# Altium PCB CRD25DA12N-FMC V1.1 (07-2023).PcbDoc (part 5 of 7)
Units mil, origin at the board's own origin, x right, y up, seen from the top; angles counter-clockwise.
Board outline 8000 x 8000 mil, 6 copper layers (Top Layer, Layer 2, Layer 3, Layer 4, Layer 5, Bottom Layer), stack 91 mil thick; 542 components, 315 nets, 1585 pads, 558 vias.
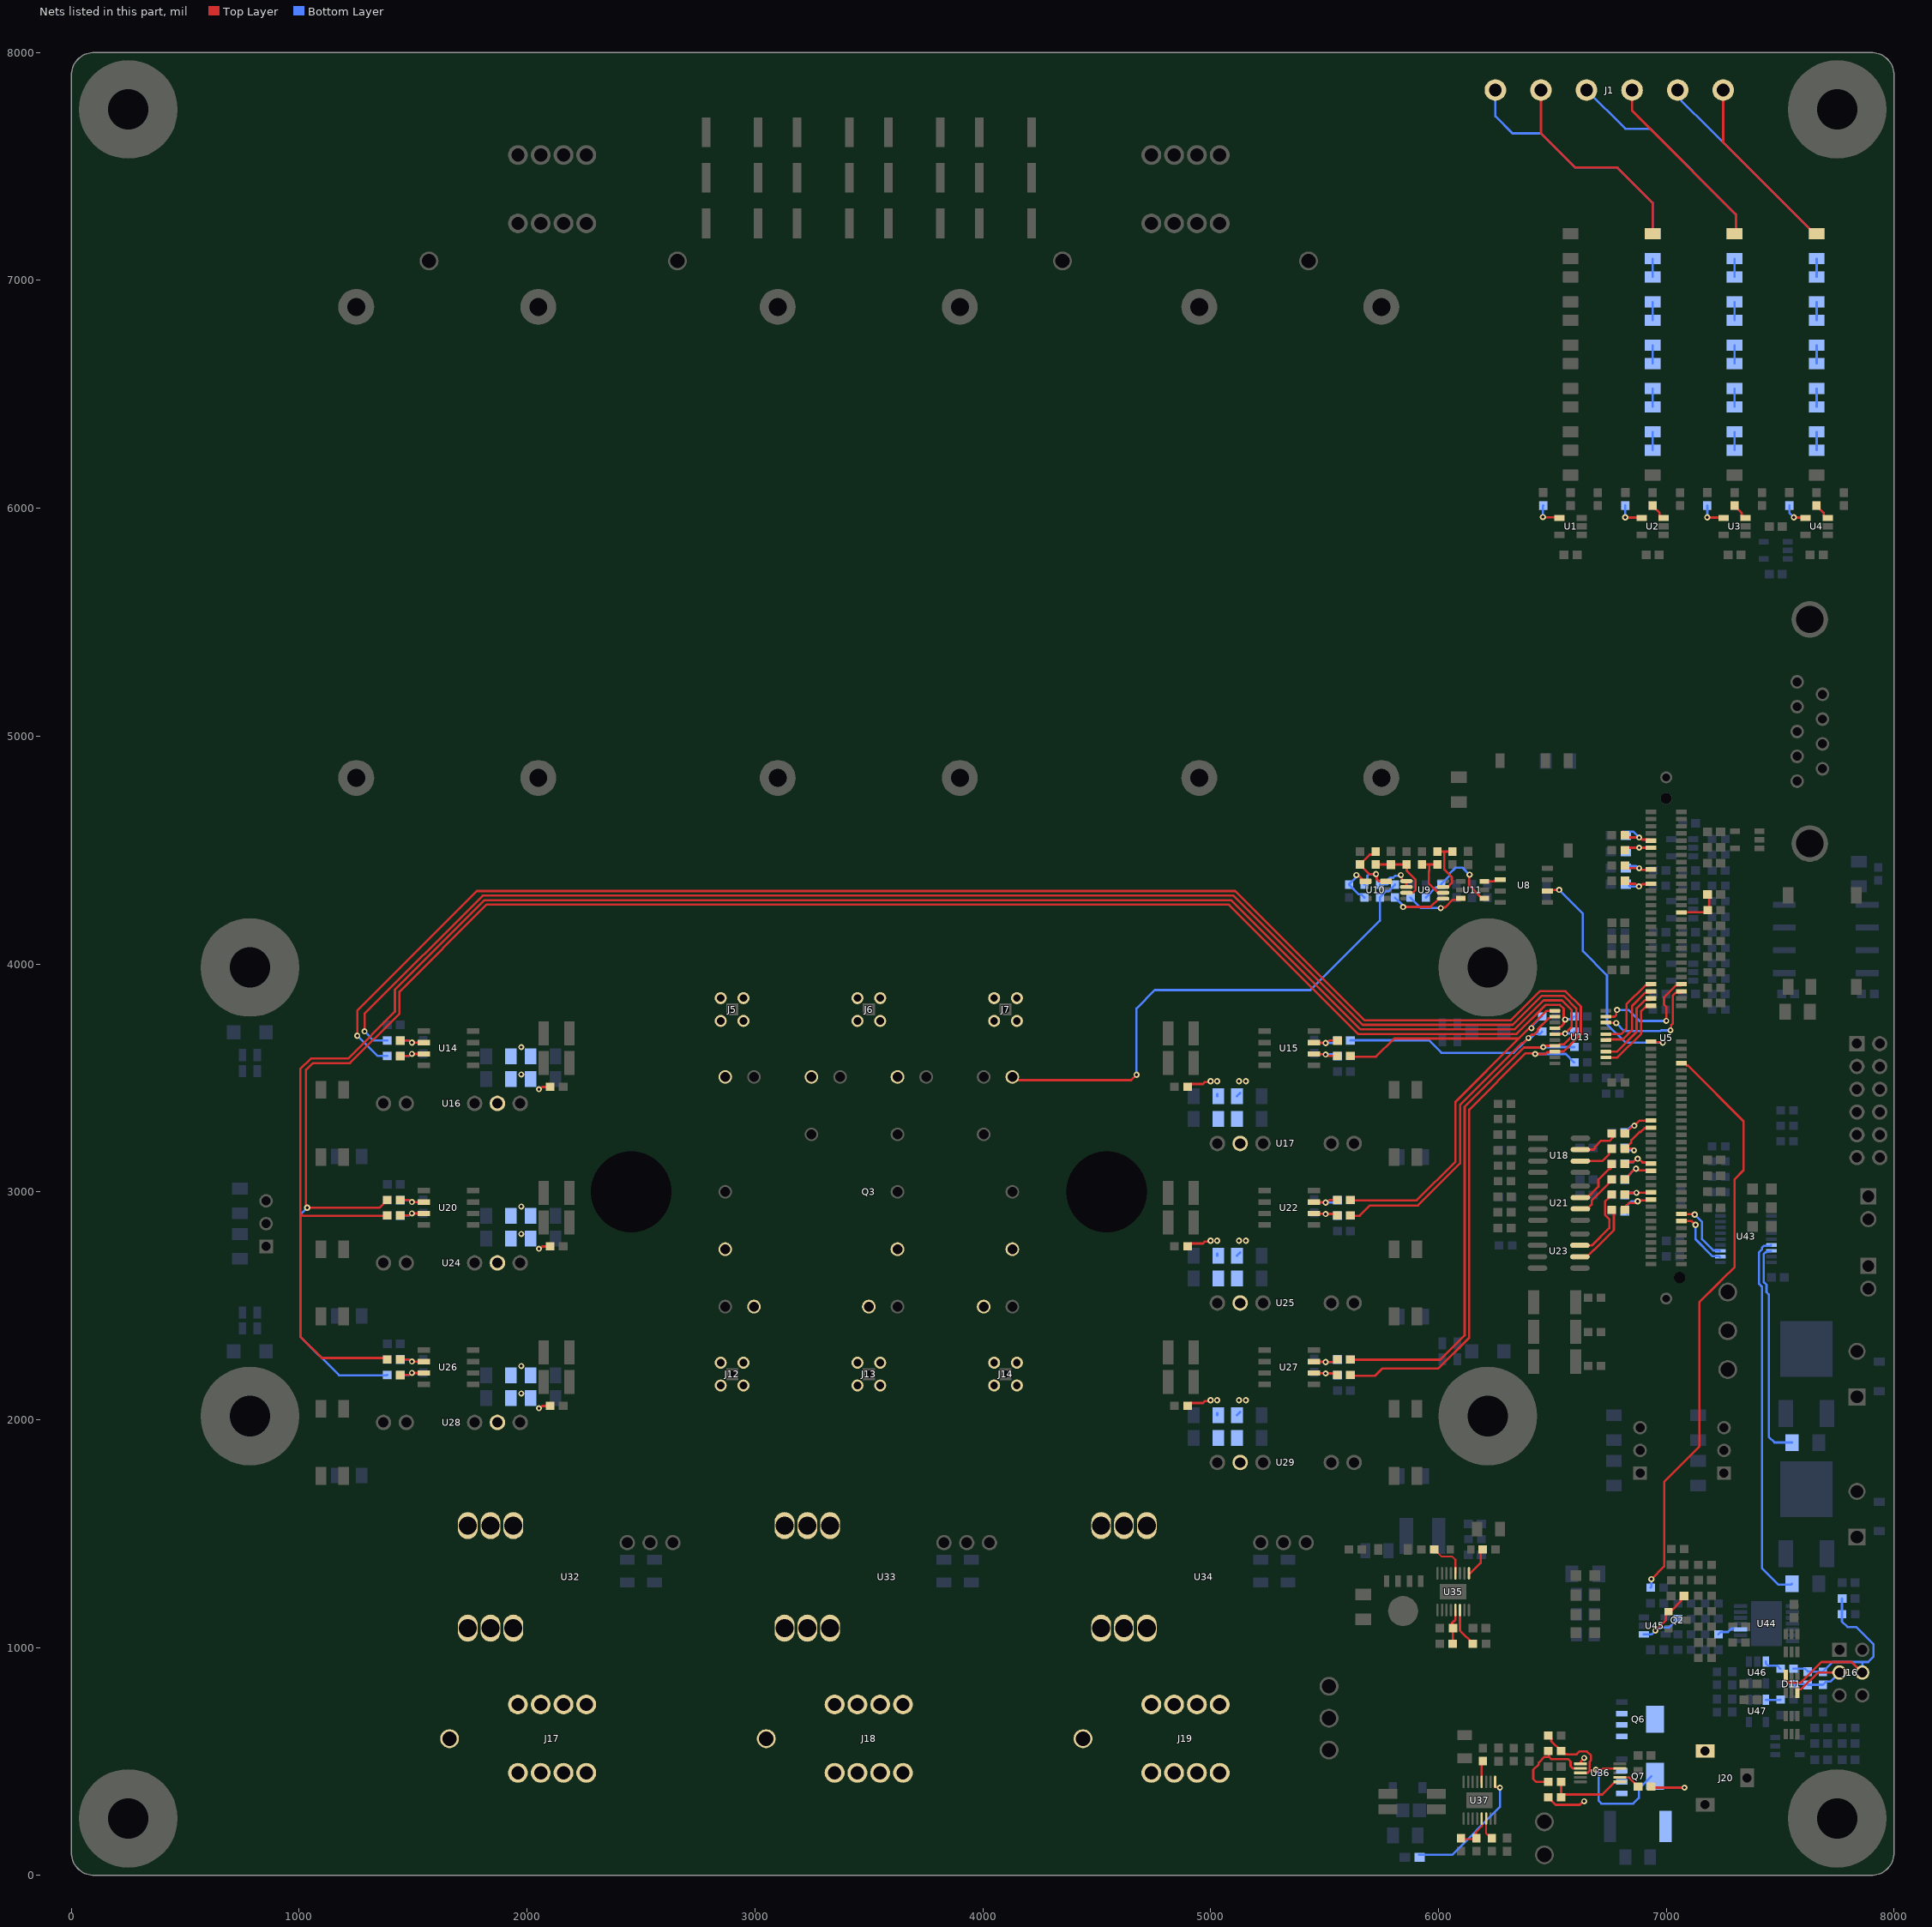
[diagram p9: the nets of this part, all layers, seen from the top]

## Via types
v1: diameter 27, hole 13, Top Layer to Bottom Layer, tented both sides, 455 vias
v2: diameter 50, hole 28, Top Layer to Bottom Layer, tented both sides, 76 vias
v3: diameter 19.68, hole 7.87, Top Layer to Bottom Layer, 27 vias

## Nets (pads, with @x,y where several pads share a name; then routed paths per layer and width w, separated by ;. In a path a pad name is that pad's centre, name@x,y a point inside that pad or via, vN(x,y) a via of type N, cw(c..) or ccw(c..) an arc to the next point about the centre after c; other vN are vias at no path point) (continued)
NetR39_2: R39.2 U2.3 | length 84.1
  Top Layer w10: R39.2@6940,6011.38 6940,6010.47 6970.59,5979.88 6970.59,5961.18 6979.37,5952.4 U2.3@6988.23,5952.4
NetR41_2: R41.2 U3.3 | length 79.1
  Top Layer w10: R41.2@7300,6011.38 7300,6010.47 7330.59,5979.88 7330.59,5966.18 7339.37,5957.4 U3.3@7348.23,5957.4
NetR43_2: R43.2 U4.3 | length 79.1
  Top Layer w10: R43.2@7660,6011.38 7660,6010.47 7690.59,5979.88 7690.59,5966.18 7699.37,5957.4 U4.3@7708.23,5957.4
NetR47_1: R47.1 R48.2 R162.2 U10.3 | length 341.8
  Top Layer w10: R47.1@5656,4436.38 5656,4435.47 5697.46,4394.02 v1(5726.14,4394.02) ; R47.1@5656,4437.28 5698.48,4479.76 5711.04,4479.76 5724,4492.72 R48.2@5724,4493.62 ; v1@5723.56,4391.44 5724.11,4391.44 5729.39,4386.16 5729.39,4372.11 5739.09,4362.4 U10.3@5780.08,4362.4
  Bottom Layer w10: R162.2@5675,4348.62 5687.96,4361.58 5687.96,4387.16 5694.81,4394.02 v1(5726.14,4394.02)
NetR50_2: R50.2 R51.1 U9.6 | length 227
  Top Layer w10: R50.2@5928,4436.38 5960,4436.38 ; R51.1@5991,4436.83 5990.54,4436.38 5960,4436.38 ; U9.6@6020.71,4312.2 5999.92,4312.2 5994.19,4317.94 5993.78,4317.94 5957.51,4354.21 5957.51,4406.31 5960,4408.8 5960,4436.38
NetR51_2: R51.2 R52.2 U9.7 | length 266.5
  Top Layer w10: R51.2@5991,4493.17 6026.27,4493.17 ; U9.7@6022.19,4339.27 6042.97,4339.27 6047.23,4343.53 6047.64,4343.53 6059.27,4355.16 6059.27,4368.13 6058.48,4368.91 6058.48,4381.68 6026.27,4413.89 6026.27,4493.17 ; R52.2@6062,4493.62 6061.54,4493.17 6026.27,4493.17
NetR68_1: R68.1 U18.7 | length 154.9
  Top Layer w10: U18.7@6638.06,3185 6680.64,3185 6686.5,3190.86 6686.5,3196.81 6714.03,3224.33 6752.28,3224.33 6765,3237.05 R68.1@6765,3240
NetR69_1: R69.1 U18.6 | length 152.8
  Top Layer w10: U18.6@6638.06,3135 6720,3135 6748.67,3163.67 6748.67,3176.04 6752.63,3180 R69.1@6765,3180
NetR70_1: R70.1 U21.7 | length 219.8
  Top Layer w10: U21.7@6623.06,2975 6654.3,2975 6702.21,3022.91 6702.21,3053.89 6747.65,3099.33 6752.28,3099.33 6765,3112.05 R70.1@6765,3115
NetR72_1: R72.1 U21.6 | length 206.2
  Top Layer w10: U21.6@6623.06,2925 6654.3,2925 6673,2943.7 6673,2961.94 6703.48,2992.42 6703.48,2992.62 6762.91,3052.05 R72.1@6762.91,3055
NetR76_1: R76.1 U23.7 | length 333.6
  Top Layer w10: U23.7@6621.11,2765 6675,2765 6750,2840 6750,2880 6731.22,2898.78 6731.22,2956.81 6747.52,2973.11 6747.52,2975.04 R76.1@6764.52,2992.05
NetR79_1: R79.1 U23.6 | length 290.1
  Top Layer w10: U23.6@6621.11,2715 6652.35,2715 6682.35,2745 6683.28,2745 6770,2831.72 6770,2912.38 R79.1@6761.38,2921
NetR99_1: R99.1 U35.4 | length 170.7
  Top Layer w8: R99.1@5983.15,1430 6013.15,1400 6060.21,1400 6074.84,1385.37 U35.4@6074.84,1346.09
  Top Layer w10: R99.1@5982.24,1430 R99.1@5983.15,1430 ; U35.4@6074.84,1325.71 U35.4@6074.84,1346.09
NetR100_1: R100.1 U35.1 | length 131.2
  Top Layer w10: U35.1@6134.18,1320 6185.39,1371.22 R100.1@6185.39,1430
NetR106_2: R106.2 R108.1 U35.13 | length 149.6
  Top Layer w8: 6074.53,1120.86 U35.13@6074.53,1164.29
  Top Layer w10: R106.2@6060.59,1090 6060.59,1109.14 6066.45,1115 6068.67,1115 6074.53,1120.86 ; R108.1@6063.03,1017 6063.03,1084.41 R106.2@6063.62,1085
NetR109_2: R109.2 U35.14 | length 174.8
  Top Layer w10: U35.14@6094.53,1164.29 6094.53,1074.33 6153.85,1015 R109.2@6154.8,1015
NetR111_2: R111.2 R114.1 U36.3 | length 358.3
  Top Layer w8: U36.3@6621.17,449.69 6655,449.69
  Top Layer w10: R111.2@6481.38,614 6482.28,614 6495.24,601.04 6495.24,588.48 6537.72,546 R114.1@6538.62,546 6551.58,533.04 6561.65,533.04 6563.19,531.5 6606.5,531.5 6618.5,543.5 6651.81,543.5 6670,525.31 6670,505 6663.1,498.1 6663.1,458.1 6655,450 6655,449.69
NetR112_1: R112.1 U37.4 | length 96.4
  Top Layer w10: U37.4@6189.84,409.25 6189.84,498.39 R112.1@6195,503.54
NetR114_2: R114.2 R116.1 U36.2 | length 405.2
  Top Layer w8: 6590,469.69 U36.2@6622.91,469.69
  Top Layer w10: R116.1@6481.38,410 6430,410 6416.5,423.5 6416.5,463.25 6440,486.75 6440,495 6465,520 6485,520 ; R114.2@6481.38,546 6485,542.38 6485,520 ; 6590,469.69 6580,479.69 6580,500 6570,510 6495,510 6485,520
NetR116_2: R116.2 R118.1 U36.6 | length 355.3
  Top Layer w8: U36.6@6774.94,410.63 U36.6@6797.09,410.63
  Top Layer w10: R116.2@6538.62,410 R118.1@6538.62,342 6551.58,354.96 6719.96,354.96 6774.04,409.04 6774.04,409.72 U36.6@6774.94,410.63
NetR117_1: R117.1 U36.7 | length 99
  Top Layer w8: U36.7@6797.09,430.32 6816,430.32 6836.06,430.32
  Top Layer w10: U36.7@6815.12,431.2 6816,430.32 U36.7@6816.9,429.41 ; 6836.06,430.32 6862.52,403.86 6862.52,402.96 6875.47,390 R117.1@6876.38,390
NetR119_1: R119.1 R120.2 U37.13 | length 148.6
  Top Layer w8: R119.1@6115.3,159.43 6164.7,159.43 6165,159.72 6165,189.49 6189.76,214.25 6189.76,247.76 U37.13@6189.84,247.83
  Top Layer w10: R119.1@6115,159.13 R119.1@6115.3,159.43
NetR121_2: R121.2 U37.14 | length 92.6
  Top Layer w8: U37.14@6209.53,247.83 6209.53,185.16 6230,164.69 R121.2@6230,163.75
NetR122_2: R122.2 R126.1 | length 79.8
  Bottom Layer w10: R126.1@7660,7015.12 R122.2@7660,7094.88
NetR123_2: R123.2 R127.1 | length 79.8
  Bottom Layer w10: R127.1@7300,7015.12 R123.2@7300,7094.88
NetR124_2: R124.2 R128.1 | length 79.8
  Bottom Layer w10: R128.1@6940,7015.12 R124.2@6940,7094.88
NetR126_2: R126.2 R130.1 | length 79.8
  Bottom Layer w10: R130.1@7660,6825.12 R126.2@7660,6904.88
NetR127_2: R127.2 R131.1 | length 79.8
  Bottom Layer w10: R131.1@7300,6825.12 R127.2@7300,6904.88
NetR128_2: R128.2 R132.1 | length 79.8
  Bottom Layer w10: R132.1@6940,6825.12 R128.2@6940,6904.88
NetR130_2: R130.2 R134.1 | length 79.8
  Bottom Layer w10: R134.1@7660,6635.12 R130.2@7660,6714.88
NetR131_2: R131.2 R135.1 | length 79.8
  Bottom Layer w10: R135.1@7300,6635.12 R131.2@7300,6714.88
NetR132_2: R132.2 R136.1 | length 79.8
  Bottom Layer w10: R136.1@6940,6635.12 R132.2@6940,6714.88
NetR134_2: R134.2 R138.1 | length 79.8
  Bottom Layer w10: R138.1@7660,6445.12 R134.2@7660,6524.88
NetR135_2: R135.2 R139.1 | length 79.8
  Bottom Layer w10: R139.1@7300,6445.12 R135.2@7300,6524.88
NetR136_2: R136.2 R140.1 | length 79.8
  Bottom Layer w10: R140.1@6940,6445.12 R136.2@6940,6524.88
NetR138_2: R138.2 R142.1 | length 79.8
  Bottom Layer w10: R142.1@7660,6255.12 R138.2@7660,6334.88
NetR139_2: R139.2 R143.1 | length 79.8
  Bottom Layer w10: R143.1@7300,6255.12 R139.2@7300,6334.88
NetR140_2: R140.2 R144.1 | length 79.8
  Bottom Layer w10: R144.1@6940,6255.12 R140.2@6940,6334.88
NetR147_2: R147.2 U4.4 | length 112.5
  Top Layer w10: v1(7560,5960) 7561.3,5958.7 7610.47,5958.7 U4.4@7611.77,5957.4
  Bottom Layer w10: R147.2@7540,6011.38 7540,5980 v1(7560,5960)
NetR149_2: R149.2 U3.4 | length 124.2
  Top Layer w10: v1(7180,5960) 7181.3,5958.7 7250.47,5958.7 U3.4@7251.77,5957.4
  Bottom Layer w10: v1(7180,5960) R149.2@7180,6011.38
NetR151_2: R151.2 U2.4 | length 124.2
  Top Layer w10: v1(6820,5960) 6821.3,5958.7 6890.47,5958.7 U2.4@6891.77,5957.4
  Bottom Layer w10: v1(6820,5960) R151.2@6820,6011.38
NetR153_2: R153.2 U1.4 | length 125.4
  Top Layer w10: v1(6458.58,5961.42) 6460.59,5959.41 6529.76,5959.41 U1.4@6531.77,5957.4
  Bottom Layer w10: v1(6458.58,5961.42) 6458.58,6009.96 R153.2@6460,6011.38
NetR157_2: R157.2 R158.1 U11.4 | length 403.6
  Top Layer w10: v1(6136.75,4391.89) 6135,4390.14 6135,4343.94 6191.34,4287.6 U11.4@6201.18,4287.6
  Bottom Layer w10: R158.1@5945,4291.38 5945,4292.28 5987.48,4334.76 5999.04,4334.76 R157.2@6012,4347.72 ; R157.2@6012,4348.62 6012,4349.53 6050.07,4387.59 6050.07,4397.39 6075.18,4422.5 6106.5,4422.5 6136.75,4392.25 v1(6136.75,4391.89)
NetR159_2: R159.2 U11.3 | length 258.2
  Top Layer w10: v1(6010,4245) 6013.25,4248.25 6029.63,4248.25 6063.15,4281.77 6092.99,4281.77 U11.3@6098.82,4287.6
  Bottom Layer w10: R159.2@5878,4291.38 5878,4290.47 5923.47,4245 v1(6010,4245)
NetR160_1: R160.1 U9.5 | length 246.8
  Top Layer w10: v1(5845,4250) 5965.39,4250 6002.01,4286.61 U9.5@6020.71,4286.61
  Bottom Layer w10: R160.1@5810,4291.38 5810,4290.47 5841.75,4258.73 5841.75,4253.25 v1(5845,4250)
NetR161_2: R161.2 U9.1 U9.2 | length 191.4
  Top Layer w10: v1(5835,4390) 5835,4385.4 5839.11,4381.29 5839.11,4366.95 5842.68,4363.39 U9.1@5859.29,4363.39 U9.2@5859.29,4337.8
  Bottom Layer w10: R161.2@5743,4348.62 5775.19,4348.62 5781.04,4354.48 5781.04,4372.04 5787.49,4378.48 5801.5,4378.48 5809.76,4386.75 5831.75,4386.75 v1(5835,4390)
NetR162_1: R162.1 R163.2 U10.4 | length 207.8
  Top Layer w10: v1(5640,4390) 5643.25,4386.75 5651.21,4386.75 5675.55,4362.4 U10.4@5689.92,4362.4
  Bottom Layer w10: v1(5640,4390) 5636.75,4386.75 5636.75,4378.27 5608,4349.53 5608,4347.72 5650.48,4305.24 5662.04,4305.24 5675,4292.28 R162.1@5675,4291.38
NetR217_1: R217.1 U44.3 | length 76.6
  Bottom Layer w10: R217.1@7228.62,1058 7238.6,1067.98 7271.26,1067.98 7286.55,1083.27 7294.76,1083.27
NetR220_2: R220.2 U46.3 | length 82.1
  Bottom Layer w10: U46.3@7437.4,938.23 7437.4,929.37 7446.18,920.59 7486.88,920.59 7500.47,907 R220.2@7501.38,907
NetR224_2: R224.2 U47.3 | length 64.4
  Bottom Layer w10: U47.3@7437.4,770 7500.38,770 R224.2@7501.38,771
NetR230_1: R230.1 U37.1 | length 571.8
  Top Layer w10: U37.1@6248.9,410.71 6248.9,388.33 6248.98,388.25 6266.75,388.25 v1(6270,385)
  Bottom Layer w10: R230.1@5915,90 6060,90 6270,300 v1(6270,385)
NTC1: Q3.NTC2 R160.2 R161.1 | length 2273.2
  Top Layer w10: Q3.NTC2@4129.92,3503.94 4143.45,3503.94 4157.39,3490 4651.79,3490 v1@4675.13,3513.34
  Bottom Layer w10: v1@4675.13,3513.34 4675,3513.47 4675,3805 4755,3885 5438.28,3885 5743,4189.72 R161.1@5743,4291.38 5743,4292.28 5770.72,4320 5782.28,4320 5810,4347.72 R160.2@5810,4348.62
  other v1: 4675,3513.34
NTC_BIAS: C13.1 R48.1 R49.2 U9.3 | length 310
  Top Layer w10: R48.1@5724,4436.38 C13.1@5792,4436.42 C13.1@5792,4436.42 R49.2@5860,4436.38 R49.2@5860,4436.38 5861.09,4435.29 5861.09,4408.38 5900,4369.46 5900,4325 5890,4315 5888.68,4313.68 5860.77,4313.68 U9.3@5859.29,4312.2
NTC_ISO: U5.57 U8.6 | length 1060.5
  Top Layer w10: U8.6@6478.35,4325 v1(6530,4325) ; U5.57@6933.07,3659.25 6935.2,3657.13 6982.87,3657.13 v1(6985,3655)
  Bottom Layer w10: v1(6530,4325) 6634.13,4220.87 6634.13,4055.87 6740,3950 6740,3735 6820,3655 v1(6985,3655)
NTC_PWM: U8.2 U11.6 | length 75.7
  Top Layer w10: U11.6@6201.18,4362.4 6245.28,4362.4 6257.87,4375 U8.2@6271.65,4375
RELAY1: R208.1 U43.17 | length 1624.2
  Bottom Layer w10: U43.17@7459.41,2765.59 7456.69,2762.87 7428.03,2762.87 7420,2754.84 7420,2747.41 7407.58,2734.99 7407.58,2596.32 7420,2583.91 7420,1348.28 7492.43,1275.86 7547.65,1275.86 R208.1@7551.79,1280
RELAY1_OUT: U5.106 U43.3 | length 280.2
  Top Layer w10: U5.106@7066.93,2903.35 7068.6,2901.67 7123.33,2901.67 v1(7125,2900)
  Bottom Layer w10: v1(7125,2900) 7157,2868 7157,2792.03 7206.16,2742.87 7232.13,2742.87 U43.3@7235,2740
RELAY2: R205.1 U43.18 | length 960.6
  Bottom Layer w10: U43.18@7459.41,2740 7457.56,2738.15 7443.58,2738.15 7439.74,2734.31 7435.18,2734.31 7427.58,2726.71 7427.58,2604.61 7440,2592.19 7440,2560 7450,2550 7450,1925 7475,1900 7551.56,1900 R205.1@7551.79,1899.76
RELAY2_OUT: U5.108 U43.2 | length 268.3
  Top Layer w10: U5.108@7066.93,2871.85 7109.87,2871.85 v1@7126.87,2854.85
  Bottom Layer w10: v1(7128.5,2854.85) 7128.5,2792.25 7203.47,2717.28 7232.13,2717.28 U43.2@7235,2714.41
RSLV_PWM: R209.1 U5.64 | length 2593.5
  Top Layer w10: v1(6935,1300) 6990.61,1355.61 6990.61,1727.11 7145,1881.5 7145,2514.67 7230.16,2599.84 7244.66,2614.33 7300,2669.67 7300,3055 7338.86,3093.86 7338.86,3310.36 7101.55,3547.67 7095.11,3554.11 7091.36,3554.11 7080.71,3564.76 U5.64@7066.93,3564.76
  Bottom Layer w10: R209.1@6931.38,1263 6935,1266.62 v1(6935,1300)
RSLV_PWM_FILT: C41.1 Q2.1 R215.2 U45.1 | length 383.9
  Top Layer w10: v1(6952.26,1074.16) 6997.91,1119.81 6997.91,1146.65 7008.66,1157.4 Q2.1@7010.63,1157.4 ; Q2.1@7015.63,1157.4 7017.6,1157.4 7063.76,1203.57 7063.76,1213.14 7077.63,1227 C41.1@7078.58,1227
  Bottom Layer w10: U45.1@6901.77,1057.6 6935.7,1057.6 v1(6952.26,1074.16) 6956.86,1074.16 6970.8,1088.1 7012.57,1088.1 7050.47,1126 R215.2@7051.38,1126
S1: C122.2 C123.1 C127.2 C128.1 J5.2 J5.3 J5.4 J5.5 Q3.S1 R231.1 U24.6 | length 53.2
  Top Layer w10: v1(2052.3,2750) 2056.9,2750 2066.9,2760 R231.1@2101.38,2760
  other v1: 1975,2815 1975,2935
S2: C143.2 C144.1 C146.2 C147.1 J12.2 J12.3 J12.4 J12.5 Q3.S2 R234.1 U28.6 | length 53.2
  Top Layer w10: v1(2052.3,2050) 2056.9,2050 2066.9,2060 R234.1@2101.38,2060
  other v1: 1975,2115 1975,2235
S3: C91.2 C92.1 C96.2 C97.1 J6.2 J6.3 J6.4 J6.5 Q3.S3 R232.1 U16.6 | length 53.2
  Top Layer w10: v1(2052.3,3450) 2056.9,3450 2066.9,3460 R232.1@2101.38,3460
  other v1: 1975,3515 1975,3635
S4: C150.1 C151.2 C152.1 C153.2 J13.2 J13.3 J13.4 J13.5 Q3.S4 R235.1 U29.6 | length 140.7
  Top Layer w10: R235.1@4898.62,2060 4911.58,2072.96 4966.5,2072.96 4975.29,2081.75 4996.75,2081.75 v1(5000,2085)
  Bottom Layer w10: C151.2@5029.19,2020 C151.2@5029.19,2028.91 ; C150.1@5115.81,2020 C150.1@5130,2034.19
  other v1: 5029.19,2085 5125,2085 5155,2085
S5: C98.1 C99.2 C100.1 C101.2 J7.2 J7.3 J7.4 J7.5 Q3.S5 R233.1 U17.6 | length 140.7
  Top Layer w10: R233.1@4898.62,3460 4911.58,3472.96 4966.5,3472.96 4975.29,3481.75 4996.75,3481.75 v1(5000,3485)
  Bottom Layer w10: C99.2@5029.19,3420 C99.2@5029.19,3428.91 ; C98.1@5115.81,3420 C98.1@5130,3434.19
  other v1: 5029.19,3485 5125,3485 5155,3485
S6: C130.1 C131.2 C133.1 C134.2 J14.2 J14.3 J14.4 J14.5 Q3.S6 R236.1 U25.6 | length 140.7
  Top Layer w10: R236.1@4898.62,2760 4911.58,2772.96 4966.5,2772.96 4975.29,2781.75 4996.75,2781.75 v1(5000,2785)
  Bottom Layer w10: C131.2@5029.19,2720 C131.2@5029.19,2728.91 ; C130.1@5115.81,2720 C130.1@5130,2734.19
  other v1: 5029.19,2785 5125,2785 5155,2785
SIN: C16.1 R55.2 U5.30 | length 184.6
  Top Layer w10: U5.30@7066.93,4226.18 7171.56,4226.18 R55.2@7181.38,4236 ; R55.2@7187.44,4240 7188.72,4241.28 7188.72,4303.72 C16.1@7190,4305
SIN_N: C168.2 C173.2 D11.6 J16.4 R214.2 R220.1 R221.1 | length 1200.7
  Top Layer w10: D11.6@7524.41,879.37 7528.27,875.51 7528.27,854.05 7536.59,845.73 7590,845.73 7669.27,925 7670,925 7681.5,936.5 7813.5,936.5 J16.4@7860,890
  Bottom Layer w10: R220.1@7558.62,907 7609.53,907 C173.2@7622,894.53 ; C173.2@7622,893.58 7689.96,893.58 7689.96,896.48 7729.97,936.5 7860,936.5 ; C168.2@7771.42,1215 C168.2@7771.42,1215 R214.2@7771.38,1146 7771.38,1113.62 7795,1090 7834.14,1090 7910,1014.14 7910,960 7886.5,936.5 7860,936.5 ; J16.4@7850,900 J16.4@7860,890 7860,936.5
SIN_P: C173.1 D11.3 J16.3 R221.2 R223.1 | length 453.9
  Top Layer w10: D11.3@7575.59,800.63 7575.59,813.11 7579.45,816.96 7591.96,816.96 7665,890 J16.3@7760,890
  Bottom Layer w10: R223.1@7558.62,839 7619.42,839 7622,836.42 R221.2@7688,836.38 7688,837.28 7700.96,850.24 7720.24,850.24 J16.3@7760,890
U: Q3.U U32.4 U32.5 U32.6
U_HI_OC: C102.1 R68.2 U5.79 | length 191.4
  Top Layer w10: R68.2@6818.62,3256 6819.53,3256 6850.27,3286.75 6856.75,3286.75 6882.8,3312.8 U5.79@6933.07,3312.8
  Bottom Layer w10: C102.1@6818.58,3261 6819.53,3261 6845.27,3286.75 6856.75,3286.75 v1(6860,3290)
U_HS: R77.1 R176.2 R204.1 U13.14 | length 8340.1
  Top Layer w10: R77.1@1386.38,2964 1385.47,2964 1351.47,2930 v1(1035,2930) 1031.75,2933.25 1031.75,2942.61 1030,2944.36 1030,3535 1060,3565 1222.55,3565 1440,3782.45 1440,3878.43 1821.57,4260 5080,4260 5647.28,3692.72 6342.57,3692.72 6469.85,3820 6533.43,3820 6550,3803.43 v1@6550,3755 ; U13.14@6510.59,3717.36 6526.34,3717.36 6533.06,3724.08 6537.62,3724.08 6550,3736.46 v1@6550,3755 ; v1(6556.77,3755.76) 6550.76,3755.76 v1@6550,3755
  Bottom Layer w10: v1(1035,2930) 1005,2900 1005,2365 1175,2195 1385.38,2195 R204.1@1386.38,2196 ; v1(6556.77,3755.76) 6558.05,3757.04 6583.42,3757.04 R176.2@6596.38,3770
U_HS+_FILT: C115.1 R77.2 U20.2 | length 162
  Top Layer w10: R77.2@1443.62,2964 1481.4,2964 1490.4,2955 v1(1495,2955) U20.2@1546.73,2955
  Bottom Layer w10: C115.1@1443.58,2964 1481.4,2964 1490.4,2955 v1(1495,2955)
U_HS-_FILT: C36.1 R204.2 U26.3 | length 162
  Top Layer w10: C36.1@1443.58,2196 1481.4,2196 1490.4,2205 v1(1495,2205) U26.3@1546.73,2205
  Bottom Layer w10: R204.2@1443.62,2196 1481.4,2196 1490.4,2205 v1(1495,2205)
U_HS_PWM: U5.49 U13.6 | length 353.2
  Top Layer w10: U13.6@6735,3691.77 6801.77,3691.77 6825,3715 6825,3822.63 6906.98,3904.61 6930.16,3904.61 U5.49@6935,3909.45
U_LO_OC: C103.1 R69.2 U5.81 | length 250
  Top Layer w10: v1@6855,3189.96 6858.45,3186.51 v1(6858.45,3181.91) ; v1@6855,3190 R69.2@6820.53,3190 ; U5.81@6933.07,3281.3 6931.77,3280 6905,3280 6887.5,3262.5 6882.19,3262.5 6846.5,3226.81 6846.5,3215 6845.53,3215 R69.2@6820.53,3190 ; R69.2@6820.53,3190 6819.62,3190 R69.2@6818.62,3189 6819.53,3189 R69.2@6820.53,3190
  Bottom Layer w10: C103.1@6818.58,3192 6828.67,3181.91 v1(6858.45,3181.91)
U_LS: R80.1 R91.1 R179.2 U13.15 | length 8433.7
  Top Layer w10: 1006.5,2904.36 1015.86,2895 R80.1@1386.38,2895 ; R91.1@1386.38,2264 1379.75,2270.63 1099.37,2270.63 1005,2365 1005,2904.36 1005,3538.28 1051.72,3585 1214.27,3585 1420,3790.73 1420,3886.72 1813.28,4280 5090,4280 5657.28,3712.72 6334.28,3712.72 6461.57,3840 6541.72,3840 6585.27,3796.45 6585.27,3724.28 6554.37,3693.39 6512.2,3693.39 U13.15@6510.59,3691.77
  Bottom Layer w10: v1(6555.98,3695) 6588.38,3695 R179.2@6596.38,3703
U_LS+_FILT: C138.1 R91.2 U26.2 | length 162
  Top Layer w10: R91.2@1443.62,2264 1481.4,2264 1490.4,2255 v1(1495,2255) U26.2@1546.73,2255
  Bottom Layer w10: C138.1@1443.58,2264 1481.4,2264 1490.4,2255 v1(1495,2255)
U_LS-_FILT: C120.1 R80.2 U20.3 | length 162
  Top Layer w10: R80.2@1443.62,2896 1481.4,2896 1490.4,2905 v1(1495,2905) U20.3@1546.73,2905
  Bottom Layer w10: C120.1@1443.58,2896 1481.4,2896 1490.4,2905 v1(1495,2905)
U_LS_PWM: U5.51 U13.5 | length 349.9
  Top Layer w10: U13.5@6735,3666.18 6737.72,3668.9 6808.84,3668.9 6850,3710.05 6850,3816.13 6906.98,3873.11 6930.16,3873.11 U5.51@6935,3877.95
U_OUT: J17.1 J17.2 J17.3 J17.4 J17.5 J17.6 J17.7 J17.8 TP10.1 U32.1 U32.2 U32.3
V: Q3.V U33.4 U33.5 U33.6
V_HI_OC: C107.1 R70.2 U5.91 | length 197.9
  Top Layer w10: R70.2@6822.09,3115 6822.09,3117.95 6834.8,3130.67 6855.15,3130.67 6869.65,3145.16 v1(6874.25,3145.16) 6878.85,3145.16 6895.35,3128.66 6928.23,3128.66 U5.91@6933.07,3123.82
  Bottom Layer w10: C107.1@6822.09,3116.97 6835.79,3130.67 6855.15,3130.67 6869.65,3145.16 v1(6874.25,3145.16)
V_HS: R92.1 R181.1 R184.2 U13.17 | length 8454.3
  Top Layer w10: v1(1286.73,3704.04) 1286.73,3781.73 1805,4300 5100,4300 5667.28,3732.72 6326,3732.72 6453.28,3860 6550,3860 6605.27,3804.73 6605.27,3700.27 6552.31,3647.31 6533.06,3647.31 6526.34,3640.59 6470.19,3640.59 6464.6,3635 v1(6460,3635) 6458.33,3633.33 6375.05,3633.33 6115,3373.28 6115,2370 6007.8,2262.8 5614.83,2262.8 R92.1@5613.62,2264
  Bottom Layer w10: v1(1286.73,3704.04) 1326.76,3664 R181.1@1386.38,3664 ; v1(6460,3635) 6595.38,3635 R184.2@6596.38,3636
V_HS+_FILT: C24.1 R181.2 U14.2 | length 162
  Top Layer w10: C24.1@1443.58,3664 1481.4,3664 1490.4,3655 v1(1495,3655) U14.2@1546.73,3655
  Bottom Layer w10: R181.2@1443.62,3664 1481.4,3664 1490.4,3655 v1(1495,3655)
V_HS-_FILT: C139.1 R92.2 U27.3 | length 164.7
  Top Layer w10: U27.3@5453.27,2255 5454.37,2253.9 5503.9,2253.9 v1(5505,2252.8) 5545.17,2252.8 R92.2@5556.38,2264
  Bottom Layer w10: v1(5505,2252.8) 5545.22,2252.8 C139.1@5556.42,2264
V_HS_PWM: U5.53 U13.3 | length 356.1
  Top Layer w10: U13.3@6735,3615 6783.23,3615 6870,3701.77 6870,3804.64 6906.98,3841.61 6930.16,3841.61 U5.53@6935,3846.46
V_LO_OC: C108.1 R72.2 U5.93 | length 204.7
  Top Layer w10: R72.2@6820,3055 6820,3057.95 6863.81,3101.76 v1(6867.48,3101.76) 6872.08,3101.76 6880.33,3093.5 6931.89,3093.5 U5.93@6933.07,3092.32
  Bottom Layer w10: C108.1@6833.7,3057.16 6827.37,3063.48 6826.52,3063.48 6864.79,3101.76 v1(6867.48,3101.76)
V_LS: R94.1 R186.1 R187.2 U13.18 | length 8711.8
  Top Layer w10: v1(1255,3685) 1255,3795 1780,4320 5108.28,4320 5675.57,3752.72 6317.72,3752.72 6445,3880 6558.28,3880 6625.27,3813.02 6625.27,3691.98 6549.21,3615.93 6511.52,3615.93 6507.72,3612.13 6477.43,3612.13 6470.14,3604.83 6425.17,3604.83 v1@6425.08,3604.92 ; R94.1@5613.62,2196 5616.83,2192.8 5722.8,2192.8 5754.76,2224.76 5999.76,2224.76 6135,2360 6135,3360 6383.25,3608.25 6401.5,3608.25 6401.67,3608.08 6421.75,3608.08 v1(6425,3604.83)
  Bottom Layer w10: v1(1255,3685) 1344,3596 R186.1@1386.38,3596 ; v1(6425,3604.83) 6425.17,3605 6558.47,3605 6595.47,3568 R187.2@6596.38,3568
V_LS+_FILT: C142.1 R94.2 U27.2 | length 161.1
  Top Layer w10: U27.2@5453.27,2205 5454.37,2203.9 5503.9,2203.9 v1(5505,2202.8) 5549.58,2202.8 R94.2@5556.38,2196
  Bottom Layer w10: v1(5505,2202.8) 5549.63,2202.8 C142.1@5556.42,2196
V_LS-_FILT: C26.1 R186.2 U14.3 | length 162
  Top Layer w10: C26.1@1443.58,3596 1481.4,3596 1490.4,3605 v1(1495,3605) U14.3@1546.73,3605
  Bottom Layer w10: R186.2@1443.62,3596 1481.4,3596 1490.4,3605 v1(1495,3605)
V_LS_PWM: U5.55 U13.2 | length 351.8
  Top Layer w10: U13.2@6735,3589.41 6785.92,3589.41 6890,3693.49 6890,3793.14 6908.75,3811.89 6931.93,3811.89 U5.55@6935,3814.96
V_OUT: J18.1 J18.2 J18.3 J18.4 J18.5 J18.6 J18.7 J18.8 TP11.1 U33.1 U33.2 U33.3
VDC_MEAS: C72.1 R54.2 U5.21 | length 205.5
  Top Layer w10: R54.2@6812.09,4355 6815.04,4352.04 6863.36,4352.04 6875.4,4340 6884.6,4340 6894.45,4349.85 6934.45,4349.85 U5.21@6935,4350.39
  Bottom Layer w10: C72.1@6822.55,4365 6837.47,4350.08 6837.47,4342.89 6840.36,4340 v1(6880,4340)
VIN: J20.1 Q6.5 R117.2 R118.2 U36.1 | length 359.9
  Top Layer w10: R118.2@6481.38,342 6482.28,342 6514.28,310 6620.4,310 6635.4,325 v1(6640,325) ; U36.1@6622.91,489.37 6624.09,489.37 6625,490.27 6625,500 v1(6640,515) ; R117.2@6933.62,390 6938.62,385 v1(7080,385)
VIN_MID: Q6.1 Q6.2 Q6.3 Q7.1 Q7.2 Q7.3
VIN_PROTECT: Q7.5 R229.1 U36.9 | length 558.8
  Top Layer w8: v1(6691.6,463.14) 6693.29,464.84 6717.1,464.84 6721.1,468.84 6795.93,468.84 U36.9@6796.93,469.84
  Bottom Layer w10: v1(6691.6,463.14) 6691.6,458.54 6703.35,446.79 6703.35,327.08 6715.43,315 6855,315 6880,340 6880,380 Q7.5@6935,435
VU_MEAS: C65.1 R45.2 U5.9 | length 225.3
  Top Layer w10: R45.2@6808.54,4580 6808.54,4577.05 6821.26,4564.33 6824.21,4564.33 6833.54,4555 v1(6881.1,4555) 6885.7,4555 6894.72,4545.98 6928.23,4545.98 U5.9@6933.07,4541.14
  Bottom Layer w10: C65.1@6808.54,4580 6856.1,4580 v1(6881.1,4555)
VU_N: J1.2 R122.1 | length 888.5
  Bottom Layer w10: J1.2@7050,7835 7066.17,7818.83 7066.17,7788.83 7190,7665 7190.28,7665 7650.16,7205.12 R122.1@7660,7205.12
VU_P: J1.1 R16.1 | length 805.5
  Top Layer w10: J1.1@7250,7835 7250,7605.28 7650.16,7205.12 R16.1@7660,7205.12
VV_MEAS: C66.1 R46.2 U5.11 | length 204
  Top Layer w10: R46.2@6808.54,4505 6813.54,4510 v1(6881.1,4510) 6881.28,4509.82 6933.05,4509.82 U5.11@6935,4507.87
  Bottom Layer w10: C66.1@6808.54,4505 6813.54,4510 v1(6881.1,4510)
VV_N: J1.4 R123.1 | length 967.7
  Bottom Layer w10: J1.4@6650,7835 6820,7665 6930,7665 7305,7290 7305,7210.12 R123.1@7300,7205.12
VV_P: J1.3 R15.1 | length 820.4
  Top Layer w10: J1.3@6850,7835 6850,7745 7305,7290 7305,7210.12 R15.1@7300,7205.12
VW_MEAS: C68.1 R53.2 U5.17 | length 206
  Top Layer w10: R53.2@6808.54,4430 6818.54,4420 v1(6881.1,4420) 6885.7,4420 6892.32,4413.39 U5.17@6935,4413.39
  Bottom Layer w10: C68.1@6812.55,4430 6866.5,4430 6876.5,4420 v1(6881.1,4420)
VW_N: J1.6 R124.1 | length 1097.3
  Bottom Layer w10: J1.6@6250,7835 6250,7720 6325,7645 6450,7645 6600,7495 6785,7495 6940,7340 R124.1@6940,7205.12
VW_P: J1.5 R14.1 | length 941.2
  Top Layer w10: J1.5@6450,7835 6450,7645 6600,7495 6785,7495 6940,7340 R14.1@6940,7205.12
W: Q3.W U34.4 U34.5 U34.6
W_HI_OC: C113.1 R76.2 U5.99 | length 161.7
  Top Layer w10: R76.2@6823.54,2995 6823.85,2995.31 v1(6869.39,2995.31) 6870.65,2996.57 6931.81,2996.57 U5.99@6933.07,2997.83
  Bottom Layer w10: C113.1@6823.54,2995 6823.85,2995.31 v1(6869.39,2995.31) ; v1@6869.39,3000.31 v1@6874.39,3000.31
W_HS: R62.1 R78.1 R177.2 U13.11 | length 2247.7
  Top Layer w10: R78.1@5613.62,2964 5614.83,2962.8 5904.51,2962.8 6075,3133.28 6075,3395 6352.5,3672.5 ; R62.1@5613.62,3596 5616.83,3592.8 5725.86,3592.8 5805.78,3672.72 6352.28,3672.72 6352.5,3672.5 ; v1(6408.14,3717.98) v1@6403.06,3723.06 ; U13.11@6510.59,3794.13 6474.13,3794.13 v1@6403.06,3723.06 ; 6352.5,3672.5 v1@6403.06,3723.06
  Bottom Layer w10: v1(6408.14,3717.98) 6411.39,3721.23 6411.39,3727.3 6454.09,3770 R177.2@6455,3770
W_HS+_FILT: C90.1 R62.2 U15.2 | length 161.1
  Top Layer w10: U15.2@5453.27,3605 5454.37,3603.9 5503.9,3603.9 v1(5505,3602.8) 5509.6,3602.8 5516.4,3596 R62.2@5556.38,3596
  Bottom Layer w10: v1(5505,3602.8) 5549.63,3602.8 C90.1@5556.42,3596
W_HS-_FILT: C116.1 R78.2 U22.3 | length 164.7
  Top Layer w10: U22.3@5453.27,2955 5454.37,2953.9 5503.9,2953.9 v1(5505,2952.8) 5509.6,2952.8 5520.8,2964 R78.2@5556.38,2964
  Bottom Layer w10: v1(5505,2952.8) 5545.22,2952.8 C116.1@5556.42,2964
W_HS_PWM: U5.50 U13.9 | length 518.5
  Top Layer w10: U13.9@6735,3768.54 6773.62,3768.54 6780.61,3775.53 6780.61,3795 v1(6783.87,3798.26) ; v1(7000,3750) 7000,3811.69 6990,3821.69 6990,3853.77 7040.83,3904.61 7064.02,3904.61 U5.50@7068.86,3909.45
  Bottom Layer w10: v1(6783.87,3798.26) 6834.2,3798.26 6882.46,3750 v1(7000,3750)
W_LO_OC: C119.1 R79.2 U5.101 | length 224.3
  Top Layer w10: R79.2@6823.54,2935 6823.54,2937.95 6836.26,2950.67 6861.87,2950.67 6869.86,2958.65 v1(6874.46,2958.65) ; v1@6874.4,2960.32 6876.53,2962.44 6932.87,2962.44 U5.101@6935,2964.57
  Bottom Layer w10: C119.1@6818.58,2915 C119.1@6830,2903.58 ; C119.1@6820,2915 6820,2931.46 6823.54,2935 6823.54,2936.97 6837.24,2950.67 6839.21,2950.67 6845.9,2957.36 6873.16,2957.36 v1(6874.46,2958.65)
W_LS: R81.1 R180.2 R182.1 U13.12 | length 2317.9
  Top Layer w10: R81.1@5613.62,2896 5614.62,2895 5655,2895 5700,2940 5910,2940 6095,3125 6095,3381.57 6366.76,3653.33 6373.64,3653.33 v1(6395.15,3674.85) 6395.15,3675.12 6409.51,3689.48 6419.94,3689.48 6436.64,3706.18 6436.64,3714.9 6483.57,3761.83 6488.13,3761.83 6494.84,3768.54 U13.12@6510.59,3768.54
  Bottom Layer w10: R182.1@5613.62,3664 5614.62,3665 5958.66,3665 6013.66,3610 6330.3,3610 6373.92,3653.61 v1(6395.15,3674.85) 6398.41,3678.1 6407.8,3678.1 6423.19,3693.5 6445.5,3693.5 R180.2@6455,3703
W_LS+_FILT: C121.1 R81.2 U22.2 | length 161.1
  Top Layer w10: U22.2@5453.27,2905 5454.37,2903.9 5503.9,2903.9 v1(5505,2902.8) 5549.58,2902.8 R81.2@5556.38,2896
  Bottom Layer w10: v1(5505,2902.8) 5549.63,2902.8 C121.1@5556.42,2896
W_LS-_FILT: C25.1 R182.2 U15.3 | length 164.7
  Top Layer w10: U15.3@5453.27,3655 5454.37,3653.9 5503.9,3653.9 v1(5505,3652.8) 5509.6,3652.8 5520.8,3664 C25.1@5556.42,3664
  Bottom Layer w10: v1(5505,3652.8) 5545.17,3652.8 R182.2@5556.38,3664
W_LS_PWM: U5.52 U13.8 | length 504.5
  Top Layer w10: U13.8@6735,3742.95 6736.2,3741.75 6779.32,3741.75 v1(6780.52,3740.55) ; v1(7018.47,3708.51) 7021.72,3711.76 7021.72,3731.42 7028.5,3738.19 7028.5,3860.78 7040.83,3873.11 7064.02,3873.11 U5.52@7068.86,3877.95
  Bottom Layer w10: v1(6780.52,3740.55) 6816.07,3705 6973.95,3705 6977.46,3708.51 v1(7018.47,3708.51)
W_OUT: J19.1 J19.2 J19.3 J19.4 J19.5 J19.6 J19.7 J19.8 TP12.1 U34.1 U34.2 U34.3
pads on no net: HS1.1 HS1.2 HS1.4 J4.1 J4.4 J4.6 J4.8 MH1.1 MH2.1 MH3.1 MH4.1 Q3.MH1 Q3.MH2 U5. U5.1 U5.2 U5.3 U5.4 U5.5 U5.6 U5.8 U5.12 U5.14 U5.15 U5.18 U5.20 U5.23 U5.24 U5.25 U5.26 U5.27 U5.28 U5.31 U5.32 U5.41 U5.42 U5.43 U5.44 U5.45 U5.54 U5.56 U5.58 U5.59 U5.60 U5.61 U5.62 U5.63 U5.66 U5.67 U5.68 U5.69 U5.70 U5.71 U5.72 U5.73 U5.75 U5.76 U5.77 U5.78 U5.80 U5.82 U5.85 U5.86 U5.89 U5.103 U5.104 U5.105 U5.107 U5.109 U5.110 U5.113 U5.114 U5.115 U5.116 U5.117 U5.118 U5.119 U5.121 U5.122 U6.8 U10.1 U10.2 U12.8 U13.13 U13.16 U35.12 U37.3 U37.12 U43.11 U43.12 U43.13 U43.14 U43.15 U43.16 U44.7 U44.8

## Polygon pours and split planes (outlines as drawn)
GND_NTC on Layer 2 "GND_NTC_L02_P208" (solid, pour order 208): 3970,3530 3970,3445 4690,3445 4690,3530
S4 on Layer 2 "S4_L02_P194" (solid, pour order 194): 3740,2070 3790,2070 3790,2025 4610,2025 4745,2160 4745,2370 5265,2370 5265,1775 4745,1775 4745,1910 3655,1910 3425,2140 3425,2585 3740,2585
S3 on Layer 2 "S3_L02_P186" (solid, pour order 186): 18 vertices, not listed, extent 1735,3325 3555,4095
S1 on Layer 2 "S1_L02_P063" (solid, pour order 63): 23 vertices, not listed, extent 1735,2625 3075,3875
S5 on Layer 2 "S5_L02_P051" (solid, pour order 51): 20 vertices, not listed, extent 3545,3175 5265,3860
S6 on Layer 2 "S6_L02_P050" (solid, pour order 50): 18 vertices, not listed, extent 3925,2120 5265,3070
S2 on Layer 2 "S2_L02_P000" (solid, pour order 0): 18 vertices, not listed, extent 1735,1925 3075,2585
GND on Layer 2 "GND_L02_P011" (solid, pour order 11): 66 vertices, not listed, extent 490,50 7950,6175
U_OUT on Layer 2 "U_OUT_L02_P301" (solid, pour order 301): 1545,1620 1545,340 2455,340 2455,1015 2165,1305 2165,1620
V_OUT on Layer 2 "V_OUT_L02_P302" (solid, pour order 302): 2935,1620 2935,340 3845,340 3845,1015 3555,1305 3555,1620
W_OUT on Layer 2 "W_OUT_L02_P303" (solid, pour order 303): 4325,1615 4325,340 5235,340 5235,1015 4945,1305 4945,1615
GND_ISO on Layer 2 "GND_ISO_L02_P294" (solid, pour order 294): 7733.93,4445 7733.93,4366.29 7810,4366.29 7810,3845 7950,3845 7950,5595 7540,5595 7540,4445
GND_NTC on Layer 2 "GND_NTC_L02_P211" (solid, pour order 211): 6055,4575 6000,4575 6000,4520 5585,4520 5585,4235 6295,4235 6295,4925 6055,4925
U on Layer 4 "U_L04_P297" (solid, pour order 297): 1545,1000 2165,1000 2165,1390 2530,1755 2540,1765 2540,2400 2785,2645 2955,2645 2955,2845 2695,2845 2310,2460 2310,1850 2115,1655 1545,1655 1545,1580
W on Layer 4 "W_L04_P296" (solid, pour order 296): 4680,1380 4535,1525 4530,1525 4530,2615 4300,2845 4045,2845 4045,2645 4167.5,2645 4280,2532.5 4280,1000 4880,1000 4880,1380
V on Layer 4 "V_L04_P295" (solid, pour order 295): 3710,2645 3710,2845 3315,2845 3125,2655 3125,2040 2935,1850 2935,1000 3555,1000 3555,1795 3325,2025 3325,2510 3460,2645
DC+ on Layer 4 "DC+_L04_P261" (solid, pour order 261): 1091.5,3916.5 2208.5,3916.5 2305,3820 2305,3185 4638,3185 6238,4785 6238,7740 758,7740 758,4250
+3.3V on Layer 4 "+3.3V_L04_P443" (solid, pour order 443): 33 vertices, not listed, extent 5970,50 7950,6175
+5V on Layer 4 "+5V_L04_P087" (solid, pour order 87): 7565,648.03 7593.03,620 7625,620 7625,560 7425,560 7425,705 7500,705 7530,735 7530,740 7530,1895 7500,1925 7340,1925 7340,1990 7565,1990 7565,1955
-3V_V_LS on Layer 4 "-3V_V_LS_L04_P088" (solid, pour order 88): 4745,2370 5265,2370 5265,1775 4745,1775
-3V_W_LS on Layer 4 "-3V_W_LS_L04_P089" (solid, pour order 89): 4745,3070 5265,3070 5265,2475 4745,2475
-3V_W_HS on Layer 4 "-3V_W_HS_L04_P155" (solid, pour order 155): 4745,3770 5265,3770 5265,3175 4745,3175
-15V on Layer 4 "-15V_L04_P185" (solid, pour order 185): 41 vertices, not listed, extent 2385,50 5945,1620
+5V on Layer 4 "+5V_L04_P253" (solid, pour order 253): 6160,3765 6160,1665 5425,1665 5425,3765
+12V on Layer 4 "+12V_L04_P204" (solid, pour order 204): 1395,1850 1470,1850 1470,1925 1575,1925 1575,3725 490,3725 490,1680 1395,1680
-3V_U_HS on Layer 4 "-3V_U_HS_L04_P332" (solid, pour order 332): 1735,3080 2245,3080 2245,2625 1735,2625
-3V_V_HS on Layer 4 "-3V_V_HS_L04_P343" (solid, pour order 343): 1735,3780 2245,3780 2245,3325 1735,3325
-3V_U_LS on Layer 4 "-3V_U_LS_L04_P344" (solid, pour order 344): 1735,2380 2245,2380 2245,1925 1735,1925
VIN on Layer 4 "VIN_L04_P221" (solid, pour order 221): 6610,50 6610,600 7385,600 7385,50
+5V_ISO on Layer 4 "+5V_ISO_L04_P293" (solid, pour order 293): 7753.85,4445 7753.85,4390 7810,4390 7810,3845 7950,3845 7950,5595 7675,5595 7540,5595 7540,4445
+5V_NTC on Layer 4 "+5V_NTC_L04_P265" (solid, pour order 265): 6055,4575 6000,4575 6000,4520 5585,4520 5585,4235 6295,4235 6295,4925 6055,4925
DC- on Layer 3 "DC-_L03_P269" (solid, pour order 269): 1119.15,3888.85 2226.15,3888.85 2310,3805 2310,2930 4565,2930 6238,4603 6238,7740 758,7740 758,4250
+12V on Layer 3 "+12V_L03_P167" (solid, pour order 167): 49 vertices, not listed, extent 5425,50 7950,3865
+15V on Layer 3 "+15V_L03_P002" (solid, pour order 2): 7230,835 7305,760 7305,560 7950,560 7950,1205 7305,1205 7305,1040.39 7230,965 7025,965 7025,835
+5V on Layer 3 "+5V_L03_P064" (solid, pour order 64): 30 vertices, not listed, extent 5970,1915 7950,6175
+15V_U_HS on Layer 3 "+15V_U_HS_L03_P008" (solid, pour order 8): 1735,3080 2245,3080 2245,2625 1735,2625
+15V_U_LS on Layer 3 "+15V_U_LS_L03_P345" (solid, pour order 345): 1735,2380 2245,2380 2245,1925 1735,1925
+15V_V_HS on Layer 3 "+15V_V_HS_L03_P346" (solid, pour order 346): 1735,3780 2245,3780 2245,3325 1735,3325
+5V_ALT on Layer 3 "+5V_ALT_L03_P199" (solid, pour order 199): 1395,1845 1470,1845 1470,1925 1575,1925 1575,3725 490,3725 490,1680 1395,1680
+15V_W_HS on Layer 3 "+15V_W_HS_L03_P086" (solid, pour order 86): 4745,3770 5265,3770 5265,3170 4745,3170
+15V_W_LS on Layer 3 "+15V_W_LS_L03_P085" (solid, pour order 85): 4745,3070 5265,3070 5265,2475 4745,2475
+15V_V_LS on Layer 3 "+15V_V_LS_L03_P274" (solid, pour order 274): 4745,2370 5265,2370 5265,1775 4745,1775
+15V on Layer 3 "+15V_L03_P156" (solid, pour order 156): 44 vertices, not listed, extent 2380,50 5945,1515
U_OUT on Layer 3 "U_OUT_L03_P268" (solid, pour order 268): 1545,1620 1545,340 2455,340 2455,1015 2165,1305 2165,1620
V_OUT on Layer 3 "V_OUT_L03_P267" (solid, pour order 267): 2935,1620 2935,340 3845,340 3845,1015 3555,1305 3555,1620
W_OUT on Layer 3 "W_OUT_L03_P264" (solid, pour order 264): 4325,1615 4325,340 5235,340 5235,1015 4945,1305 4945,1615
+5V_ISO on Layer 3 "+5V_ISO_L03_P187" (solid, pour order 187): 7755,4445 7755,4390 7810,4390 7810,3845 7950,3845 7950,5595 7675,5595 7540,5595 7540,4445
+5V_NTC on Layer 3 "+5V_NTC_L03_P239" (solid, pour order 239): 6055,4575 6000,4575 6000,4520 5585,4520 5585,4235 6295,4235 6295,4925 6055,4925
U on Bottom Layer "U_L06_P272" (solid, pour order 272): 1545,1000 2165,1000 2165,1390 2530,1755 2540,1765 2540,2400 2785,2645 2955,2645 2955,2845 2695,2845 2310,2460 2310,1850 2115,1655 1545,1655 1545,1580
DC+ on Bottom Layer "DC+_L06_P198" (solid, pour order 198): 5308,3855 4640,3855 4638,3185 1823,3185 758,4250 758,7740 6238,7740 6238,4785
W on Bottom Layer "W_L06_P015" (solid, pour order 15): 4680,1380 4530,1530 4530,2615 4300,2845 4045,2845 4045,2645 4167.5,2645 4280,2532.5 4280,1000 4880,1000 4880,1380
V on Bottom Layer "V_L06_P013" (solid, pour order 13): 3710,2645 3710,2845 3315,2845 3125,2655 3125,2040 2935,1850 2935,1000 3555,1000 3555,1795 3325,2025 3325,2510 3460,2645
GND on Bottom Layer "GND_L06_P359" (solid, pour order 359): 7470,2109.76 7470,1944.76 7625,1944.76 7625,2109.76
+15V on Bottom Layer "+15V_L06_P238" (solid, pour order 238): 17 vertices, not listed, extent 5630,815 7165,1240
VIN on Bottom Layer "VIN_L06_P149" (solid, pour order 149): 7025,565 7070,520 7070,460 7235,460 7235,615 7165,615 7115,665 7115,805 6862.17,805 6862.17,565
+12V on Bottom Layer "+12V_L06_P442" (solid, pour order 442): 805,2785 775,2755 685,2755 685,2660 905,2660 905,2805 805,2805
GND on Bottom Layer "GND_L06_P441" (solid, pour order 441): 795,2936.88 826.88,2905 905,2905 905,2815 826.88,2815 795,2783.12 795,2765 685,2765 685,2955 795,2955
+5V_ALT on Bottom Layer "+5V_ALT_L06_P440" (solid, pour order 440): 773.12,2965 805,2933.12 805,2915 905,2915 905,3060 685,3060 685,2965
+12V on Bottom Layer "+12V_L06_P439" (solid, pour order 439): 7203.58,1790 7173.58,1760 7083.58,1760 7083.58,1665 7303.58,1665 7303.58,1810 7203.58,1810
GND on Bottom Layer "GND_L06_P438" (solid, pour order 438): 7193.58,1941.88 7225.47,1910 7303.58,1910 7303.58,1820 7225.46,1820 7193.58,1788.12 7193.58,1770 7083.58,1770 7083.58,1960 7193.58,1960
+5V on Bottom Layer "+5V_L06_P437" (solid, pour order 437): 7171.7,1970 7203.58,1938.12 7203.58,1920 7303.58,1920 7303.58,2065 7083.58,2065 7083.58,1970
GND on Bottom Layer "GND_L06_P436" (solid, pour order 436): 6530,5000 6530,4825 6638.38,4825 6638.38,5000
+5V on Bottom Layer "+5V_L06_P435" (solid, pour order 435): 6410,5000 6410,4825 6520,4825 6520,5000
NetC105_1 on Bottom Layer "NETC105_1_L06_P433" (solid, pour order 433): 6045,3085 5480,3085 5480,3295 6045,3295
NetC135_1 on Bottom Layer "NETC135_1_L06_P432" (solid, pour order 432): 6045,2385 5480,2385 5480,2595 6045,2595
NetC156_1 on Bottom Layer "NETC156_1_L06_P104" (solid, pour order 104): 6045,1685 5480,1685 5480,1895 6045,1895
-3V_W_HS on Bottom Layer "-3V_W_HS_L06_P415" (solid, pour order 415): 5265,3545 5265,3175 5180,3175 5180,3427.2 5180,3545
S5 on Bottom Layer "S5_L06_P414" (solid, pour order 414): 5039.01,3260 5094,3205 5095,3205 5095,3175 5170,3175 5170,3545 4975,3545 4975,3260
+15V_W_HS on Bottom Layer "+15V_W_HS_L06_P413" (solid, pour order 413): 4965,3555 5265,3555 5265,3770 4970,3770 4745,3770 4745,3175 5085,3175 5085,3250 5025,3250 4965,3310
-3V_W_LS on Bottom Layer "-3V_W_LS_L06_P412" (solid, pour order 412): 5265,2845 5265,2475 5180,2475 5180,2727.2 5180,2845
S6 on Bottom Layer "S6_L06_P411" (solid, pour order 411): 5039.01,2560 5094,2505 5095,2505 5095,2475 5170,2475 5170,2845 4975,2845 4975,2560
+15V_W_LS on Bottom Layer "+15V_W_LS_L06_P410" (solid, pour order 410): 4965,2855 5265,2855 5265,3070 4970,3070 4745,3070 4745,2475 5085,2475 5085,2550 5025,2550 4965,2610
S4 on Bottom Layer "S4_L06_P096" (solid, pour order 96): 5039.01,1860 5094,1805 5095,1805 5095,1775 5170,1775 5170,2145 4975,2145 4975,1860
+15V_V_LS on Bottom Layer "+15V_V_LS_L06_P093" (solid, pour order 93): 4965,2155 5265,2155 5265,2370 4970,2370 4745,2370 4745,1775 5085,1775 5085,1850 5025,1850 4965,1910
+15V_V_HS on Bottom Layer "+15V_V_HS_L06_P399" (solid, pour order 399): 2030,3425 2030,3480 2080,3480 2080,3780 2245,3780 2245,3325 1935,3325 1935,3425
-3V_V_HS on Bottom Layer "-3V_V_HS_L06_P398" (solid, pour order 398): 1820,3405.41 1850,3435 1870,3435 1870,3780 1735,3780 1735,3325 1820.86,3325 1820,3325.86
S3 on Bottom Layer "S3_L06_P397" (solid, pour order 397): 1880,3455 1850,3425 1830,3425 1830,3325 1865,3325 1925,3325 1925,3379.01 1979.01,3379.01 1980,3380 1980,3435 2070,3435 2070,3780 1880,3780
+15V_U_LS on Bottom Layer "+15V_U_LS_L06_P396" (solid, pour order 396): 2030,2025 2030,2080 2080,2080 2080,2380 2245,2380 2245,1925 1935,1925 1935,2025
-3V_U_LS on Bottom Layer "-3V_U_LS_L06_P395" (solid, pour order 395): 1820,2005.41 1850,2035 1870,2035 1870,2380 1735,2380 1735,1925 1820.86,1925 1820,1925.86
S2 on Bottom Layer "S2_L06_P394" (solid, pour order 394): 1880,2055 1850,2025 1830,2025 1830,1925 1865,1925 1925,1925 1925,1979.01 1979.01,1979.01 1980,1980 1980,2035 2070,2035 2070,2380 1880,2380
NetC106_1 on Bottom Layer "NETC106_1_L06_P387" (solid, pour order 387): 1225,3080 1225,3240 1395,3240 1395,3080
NetC106_2 on Bottom Layer "NETC106_2_L06_P386" (solid, pour order 386): 1395,3275.77 1444.23,3325 1525,3325 1525,3440 1230,3440 1230,3365 1045,3365 1045,3080 1215,3080 1215,3198.6 1265.17,3248.77 1265.17,3250 1395,3250
NetC157_1 on Bottom Layer "NETC157_1_L06_P385" (solid, pour order 385): 1225,1680 1225,1840 1395,1840 1395,1680
NetC157_2 on Bottom Layer "NETC157_2_L06_P384" (solid, pour order 384): 1395,1875.77 1444.23,1925 1525,1925 1525,2040 1230,2040 1230,1965 1045,1965 1045,1680 1215,1680 1215,1798.6 1265.17,1848.77 1265.17,1850 1395,1850
NetC136_2 on Bottom Layer "NETC136_2_L06_P255" (solid, pour order 255): 1395,2575.77 1444.23,2625 1525,2625 1525,2740 1230,2740 1230,2665 1045,2665 1045,2380 1215,2380 1215,2498.6 1265.17,2548.77 1265.17,2550 1395,2550
NetC136_1 on Bottom Layer "NETC136_1_L06_P256" (solid, pour order 256): 1225,2380 1225,2540 1395,2540 1395,2380
+15V_U_HS on Bottom Layer "+15V_U_HS_L06_P340" (solid, pour order 340): 2030,2725 2030,2780 2080,2780 2080,3080 2245,3080 2245,2625 1935,2625 1935,2725
S1 on Bottom Layer "S1_L06_P021" (solid, pour order 21): 1880,2755 1850,2725 1830,2725 1830,2625 1865,2625 1925,2625 1925,2679.01 1979.01,2679.01 1980,2680 1980,2735 2070,2735 2070,3080 1880,3080
-3V_U_HS on Bottom Layer "-3V_U_HS_L06_P028" (solid, pour order 28): 1820,2705.41 1850,2735 1870,2735 1870,3080 1735,3080 1735,2625 1820.86,2625 1820,2625.86
GND on Bottom Layer "GND_L06_P164" (solid, pour order 164): 3780,1330 3780,1240 4005,1240 4005,1330
-15V on Bottom Layer "-15V_L06_P373" (solid, pour order 373): 5170,1515 5170,1340 5270,1340 5270,1515
GND on Bottom Layer "GND_L06_P372" (solid, pour order 372): 5170,1330 5170,1240 5395,1240 5395,1330
+15V on Bottom Layer "+15V_L06_P371" (solid, pour order 371): 5280,1515 5280,1340 5395,1340 5395,1515
-15V on Bottom Layer "-15V_L06_P370" (solid, pour order 370): 2390,1515 2390,1340 2490,1340 2490,1515
GND on Bottom Layer "GND_L06_P369" (solid, pour order 369): 2390,1330 2390,1240 2615,1240 2615,1330
+15V on Bottom Layer "+15V_L06_P368" (solid, pour order 368): 2500,1515 2500,1340 2615,1340 2615,1515
+15V on Bottom Layer "+15V_L06_P159" (solid, pour order 159): 3890,1515 3890,1340 4005,1340 4005,1515
-15V on Bottom Layer "-15V_L06_P306" (solid, pour order 306): 3780,1515 3780,1340 3880,1340 3880,1515
GND_ISO on Bottom Layer "GND_ISO_L06_P292" (solid, pour order 292): 7790,4525 7790,4405 7885,4405 7885,4525
+12V on Bottom Layer "+12V_L06_P361" (solid, pour order 361): 7775,1550 7775,1415 7980,1415 7980,1550
NetD18_2 on Bottom Layer "NETD18_2_L06_P360" (solid, pour order 360): 7760,1545 7760,1560 7980,1560 7980,1840 7480,1840 7480,1545
GND on Bottom Layer "GND_L06_P225" (solid, pour order 225): 5730,315 5755,340 5840,340 5840,430 5665,430 5665,290 5730,290
VIN_MID on Bottom Layer "VIN_MID_L06_P151" (solid, pour order 151): 6850,740 6850,575 6760,575 6760,490 6850,490 6850,330 6715,330 6715,740
VIN_PROTECT on Bottom Layer "VIN_PROTECT_L06_P152" (solid, pour order 152): 6935,150 6935,120 7055,120 7055,555 6862.17,555 6862.17,150
NetD17_2 on Bottom Layer "NETD17_2_L06_P129" (solid, pour order 129): 7760,2160 7760,2175 7980,2175 7980,2455 7480,2455 7480,2160
+12V on Bottom Layer "+12V_L06_P355" (solid, pour order 355): 6835,1790 6805,1760 6715,1760 6715,1665 6935,1665 6935,1810 6835,1810
-3V_V_LS on Bottom Layer "-3V_V_LS_L06_P099" (solid, pour order 99): 5265,2145 5265,1775 5180,1775 5180,2027.2 5180,2145
+5V_ISO on Bottom Layer "+5V_ISO_L06_P290" (solid, pour order 290): 7790,4395 7790,4295 7910,4295 7910,4340 7885,4340 7885,4395
GND_ISO on Bottom Layer "GND_ISO_L06_P288" (solid, pour order 288): 7870,3930 7870,3830 7950,3830 7950,3930
+5V_ISO on Bottom Layer "+5V_ISO_L06_P287" (solid, pour order 287): 7895,4010 7815,4010 7815,3900 7815,3830 7860,3830 7860,3940 7900,3940 7950,3940 7950,4010
GND_ISO on Bottom Layer "GND_ISO_L06_P286" (solid, pour order 286): 7815,4290 7815,4210 7950,4210 7950,4290
GND on Bottom Layer "GND_L06_P285" (solid, pour order 285): 7465,3935 7465,3775 7535,3775 7535,3935
+3.3V on Bottom Layer "+3.3V_L06_P282" (solid, pour order 282): 7605,3830 7605,3910 7585,3910 7585,4010 7465,4010 7465,3945 7540,3945 7540,3830
GND on Bottom Layer "GND_L06_P281" (solid, pour order 281): 7450,4295 7450,4210 7585,4210 7585,4295
GND on Bottom Layer "GND_L06_P240" (solid, pour order 240): 6785,4635 6785,4285 6695,4285 6695,4635
NetC159_1 on Bottom Layer "NETC159_1_L06_P234" (solid, pour order 234): 5735,1525 5735,1345 5820,1345 5820,1525
GND on Bottom Layer "GND_L06_P232" (solid, pour order 232): 5625,1525 5625,1345 5725,1345 5725,1525
+12V on Bottom Layer "+12V_L06_P230" (solid, pour order 230): 5955,1605 5955,1395 6095,1395 6095,1605
NetD4_2 on Bottom Layer "NETD4_2_L06_P229" (solid, pour order 229): 5915,1355 5950,1320 5950,1300 5980,1300 5980,1355 5945,1390 5930,1390 5930,1605 5810,1605 5810,1580 5830,1560 5830,1355
GND on Bottom Layer "GND_L06_P226" (solid, pour order 226): 5880,225 5880,110 5980,110 5980,225
NetC182_1 on Bottom Layer "NETC182_1_L06_P192" (solid, pour order 192): 5980,315 6005,340 6010,345 6055,345 6055,430 5885,430 5885,235 5980,235
NetC182_2 on Bottom Layer "NETC182_2_L06_P223" (solid, pour order 223): 5875,330 5875,180 5840,180 5840,225 5785,225 5785,330
-15V on Bottom Layer "-15V_L06_P190" (solid, pour order 190): 5835,167.5 5835,165 5855,165 5855,120 5855,45 5680,45 5680,260 5770,260 5770,225 5835,225
GND on Bottom Layer "GND_L06_P222" (solid, pour order 222): 6920,115 6920,140 6880,140 6880,125 6880,25 6995,25 6995,115
+12V on Bottom Layer "+12V_L06_P220" (solid, pour order 220): 7775,2165 7775,2030 7980,2030 7980,2165
+12V on Bottom Layer "+12V_L06_P154" (solid, pour order 154): 6705,305 6705,25 6865,25 6865,140 6840,140 6840,305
